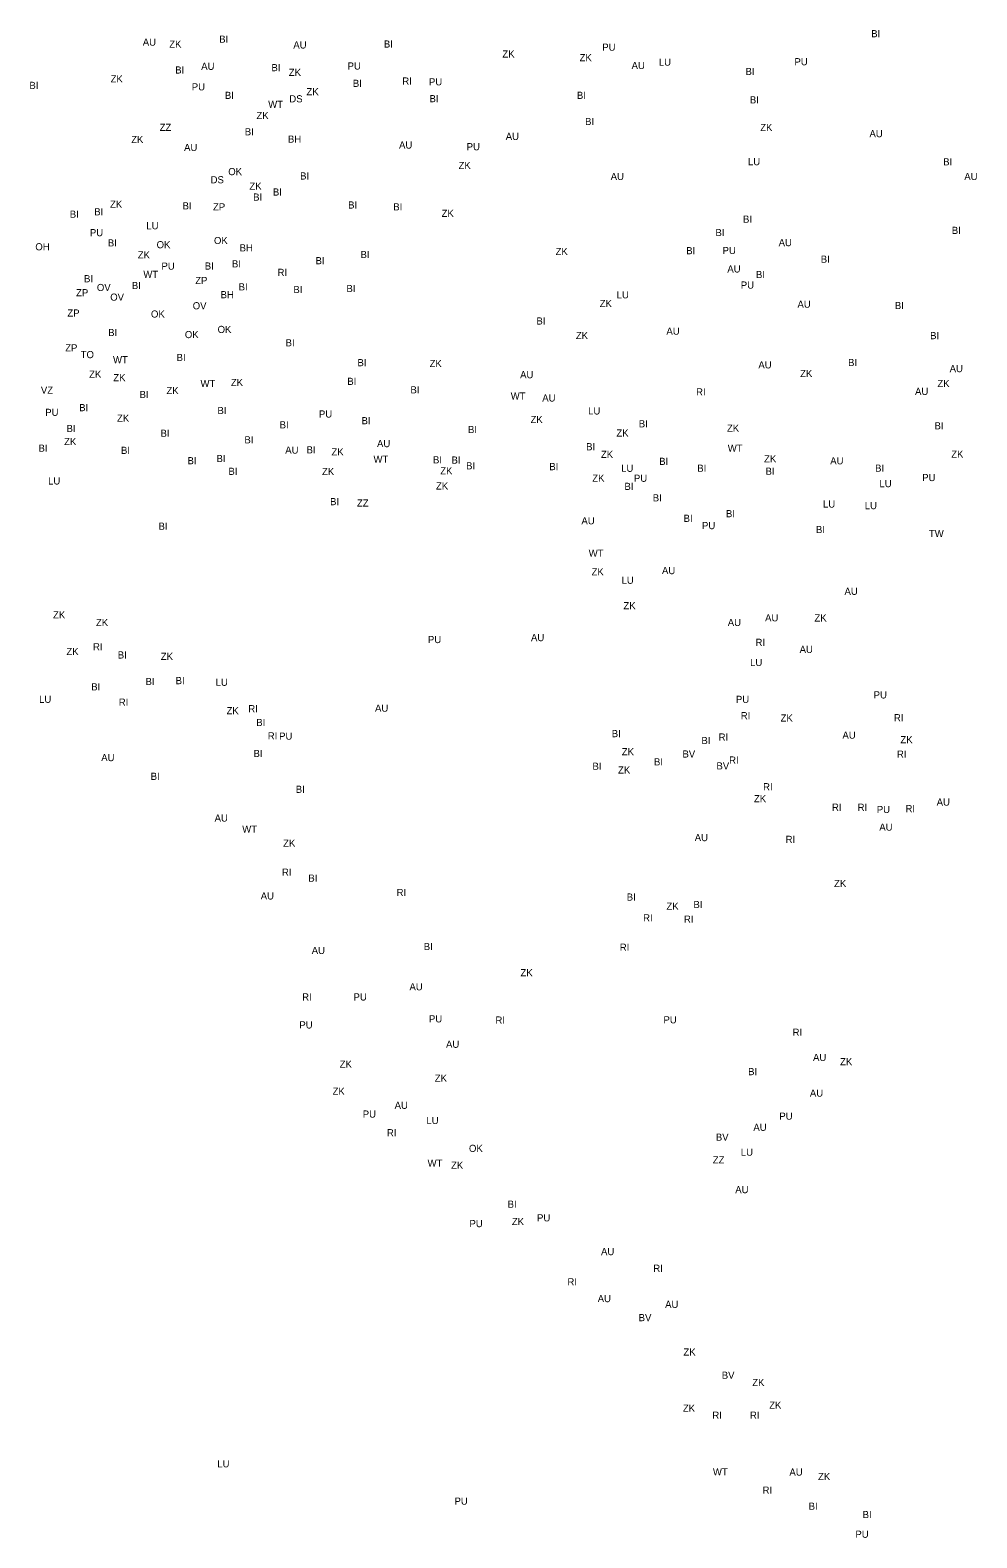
# Model space of a CAD drawing. Extents: x -439151 to -433911, y -1129946 to -1121460.
# Drawn here: x -437868 to -436541, y -1125705 to -1123591 of the extents above; entities that cross this region are included whole.
import ezdxf

# ---------------------------------------------------------------- set-up
doc = ezdxf.new("R2010")
doc.units = 0
doc.layers.add('POPIS PRESTAVBA', color=7, linetype='Continuous')
doc.layers.add('ZASTAVITELNA PLOCHA', color=7, linetype='Continuous')

msp = doc.modelspace()

# ---------------------------------------------------------------- texts
at = {"layer": 'POPIS PRESTAVBA'}
for s, p in [('AU', (-437709.7, -1123612.7)), ('BI', (-436688.8, -1123600.9)), ('ZK', (-437672.6, -1123615.5)), ('AU', (-437498.7, -1123616.7)), ('BI', (-437371.8, -1123615.4)), ('ZK', (-437205.7, -1123629.3)), ('PU', (-437065.7, -1123619.8)), ('AU', (-437627.8, -1123646.6)), ('BI', (-437529.4, -1123648.5)), ('ZK', (-437505, -1123655.1)), ('PU', (-437422.6, -1123646.2)), ('ZK', (-437097.5, -1123634.5)), ('AU', (-437024.6, -1123645.5)), ('LU', (-436986.4, -1123640.7)), ('BI', (-436864.9, -1123653.8)), ('PU', (-436796.3, -1123640.2)), ('BI', (-437868.6, -1123673.4)), ('ZK', (-437754.8, -1123664.3)), ('PU', (-437641, -1123675.4)), ('BI', (-437415.3, -1123670.5)), ('RI', (-437345.9, -1123667.3)), ('PU', (-437308.6, -1123668.4)), ('BI', (-437594.6, -1123687.4)), ('DS', (-437504.3, -1123692.2)), ('ZK', (-437480.2, -1123682.2)), ('BI', (-437307.8, -1123692)), ('BI', (-437101.2, -1123687.3)), ('BI', (-436858.8, -1123693.7)), ('ZK', (-437550.3, -1123715.6)), ('WT', (-437533.9, -1123699.9)), ('ZZ', (-437686, -1123732.2)), ('BI', (-437566.7, -1123738.4)), ('ZK', (-436844.3, -1123732.4)), ('ZK', (-437725.9, -1123749.2)), ('AU', (-437651.8, -1123760.4)), ('BH', (-437506.2, -1123748.7)), ('AU', (-437350.5, -1123757)), ('PU', (-437255.7, -1123759.4)), ('AU', (-437201, -1123744.9)), ('AU', (-436691.2, -1123741.1)), ('LU', (-436861.5, -1123780.4)), ('BI', (-436587.9, -1123780.6)), ('OK', (-437589.9, -1123794.3)), ('ZK', (-437267.1, -1123785.6)), ('AU', (-437053.9, -1123801.1)), ('AU', (-436558.3, -1123801.1)), ('DS', (-437614.6, -1123805.7)), ('ZK', (-437560.2, -1123814.6)), ('BI', (-437527.3, -1123822.9)), ('ZK', (-437755.6, -1123840)), ('BI', (-437653.9, -1123842.3)), ('ZP', (-437611.3, -1123843.7)), ('BI', (-437555, -1123830)), ('BI', (-437358.6, -1123843.7)), ('ZK', (-437290.9, -1123852.8)), ('BI', (-436868.4, -1123860.9)), ('PU', (-437783.8, -1123879.9)), ('LU', (-437704.7, -1123870.2)), ('BI', (-436575.8, -1123876.7)), ('OH', (-437860.3, -1123899.7)), ('BI', (-437758.6, -1123894.3)), ('OK', (-437690.3, -1123896.8)), ('OK', (-437609.9, -1123890.9)), ('BH', (-437573.9, -1123901.2)), ('ZK', (-437131.1, -1123906.3)), ('BI', (-436948, -1123905.2)), ('PU', (-436897.1, -1123904.9)), ('AU', (-436818.5, -1123893.9)), ('ZK', (-437716.7, -1123911.1)), ('PU', (-437683.5, -1123926.8)), ('BI', (-437622.8, -1123926.7)), ('BI', (-437584.7, -1123923.6)), ('BI', (-436759.5, -1123917.1)), ('BI', (-437792, -1123944.5)), ('WT', (-437708.9, -1123938.3)), ('ZP', (-437636.2, -1123947)), ('RI', (-437520.8, -1123935.6)), ('AU', (-436890.4, -1123930.8)), ('BI', (-436850.3, -1123938.7)), ('ZP', (-437803.2, -1123964.1)), ('OV', (-437755.3, -1123970.3)), ('BI', (-437725, -1123954)), ('BH', (-437600.6, -1123966.9)), ('BI', (-437575.3, -1123956)), ('BI', (-437424.2, -1123958.2)), ('LU', (-437045.5, -1123967)), ('PU', (-436871.5, -1123953.4)), ('ZP', (-437815.4, -1123992.6)), ('OK', (-437698.2, -1123994)), ('OV', (-437639.7, -1123982.4)), ('ZK', (-437069.3, -1123979.3)), ('AU', (-436792.1, -1123980.2)), ('BI', (-437158, -1124003.8)), ('BI', (-437758.2, -1124020)), ('OK', (-437650.7, -1124022.8)), ('OK', (-437604.8, -1124015.6)), ('BI', (-437509.5, -1124034.3)), ('ZK', (-437102.7, -1124024.2)), ('AU', (-436975.8, -1124018)), ('BI', (-436606.2, -1124024.3)), ('BI', (-437662.3, -1124054.9)), ('ZK', (-437784.8, -1124078.4)), ('WT', (-437751.4, -1124058.1)), ('BI', (-437408.8, -1124062.2)), ('ZK', (-437307.7, -1124063.5)), ('AU', (-436846.9, -1124065.3)), ('ZK', (-436788.3, -1124077.4)), ('BI', (-436721.2, -1124062)), ('AU', (-436578.8, -1124070.6)), ('ZK', (-437751, -1124083.2)), ('WT', (-437628.8, -1124091.5)), ('ZK', (-437586.2, -1124090)), ('AU', (-437180.8, -1124079.1)), ('ZK', (-436596, -1124091.5)), ('VZ', (-437852.5, -1124100.7)), ('BI', (-437714.2, -1124106.8)), ('ZK', (-437676.5, -1124101.4)), ('BI', (-437334.5, -1124100.3)), ('WT', (-437194, -1124108.9)), ('AU', (-437149.8, -1124111.8)), ('RI', (-436934.2, -1124103.2)), ('AU', (-436627.3, -1124102.5)), ('PU', (-437846.4, -1124131.9)), ('BI', (-437798.8, -1124125.3)), ('ZK', (-437745.8, -1124140)), ('BI', (-437605, -1124129.3)), ('PU', (-437462.8, -1124134.2)), ('ZK', (-437166.2, -1124141.9)), ('LU', (-437085.5, -1124129.9)), ('BI', (-437517.8, -1124149.3)), ('BI', (-437403.1, -1124143.6)), ('ZK', (-437045.9, -1124160.9)), ('BI', (-437014.5, -1124147.9)), ('ZK', (-436890.9, -1124154)), ('BI', (-436600, -1124150.7)), ('BI', (-437855.8, -1124182.1)), ('ZK', (-437819.9, -1124172.9)), ('BI', (-437567.2, -1124170.4)), ('AU', (-437381.4, -1124175.7)), ('WT', (-436889.8, -1124182.2)), ('BI', (-437740.2, -1124185.2)), ('BI', (-437647, -1124199.7)), ('BI', (-437606.3, -1124196.6)), ('AU', (-437510, -1124184.8)), ('ZK', (-437445.2, -1124187.3)), ('WT', (-437386.3, -1124197.6)), ('BI', (-437277, -1124198.8)), ('ZK', (-437067.6, -1124190.8)), ('ZK', (-436838.9, -1124197)), ('AU', (-436746.2, -1124199.8)), ('ZK', (-436576.6, -1124190.5)), ('ZK', (-437458.5, -1124214.8)), ('ZK', (-437292.8, -1124213.9)), ('BI', (-437139.9, -1124208)), ('ZK', (-437079.7, -1124224.1)), ('LU', (-437039.2, -1124210.3)), ('PU', (-437021.3, -1124224.3)), ('BI', (-436932.5, -1124210.3)), ('BI', (-436683.3, -1124210.1)), ('PU', (-436617.3, -1124223.3)), ('LU', (-437842.4, -1124228.1)), ('ZK', (-437298.8, -1124235.1)), ('LU', (-436677.2, -1124231.9)), ('BI', (-437447.2, -1124257.1)), ('ZZ', (-437409.5, -1124259)), ('BI', (-436994.9, -1124251.8)), ('LU', (-436756.3, -1124260.5)), ('LU', (-436697.8, -1124262.7)), ('AU', (-437094.9, -1124283.9)), ('BI', (-437687.6, -1124291.6)), ('PU', (-436925.9, -1124290.7)), ('TW', (-436607.9, -1124301.9)), ('WT', (-437084.7, -1124329.4)), ('ZK', (-437080.7, -1124355.5)), ('LU', (-437038.7, -1124367.3)), ('AU', (-436982, -1124353.8)), ('AU', (-436726.2, -1124382.8)), ('ZK', (-437835.5, -1124415.8)), ('ZK', (-437036, -1124403)), ('ZK', (-437775.3, -1124426.6)), ('AU', (-436889.8, -1124426.6)), ('AU', (-436837.5, -1124420)), ('ZK', (-436768.3, -1124420.2)), ('PU', (-437310, -1124450.5)), ('AU', (-437165.6, -1124447.8)), ('RI', (-436850.9, -1124454.4)), ('ZK', (-437816.7, -1124467.3)), ('RI', (-437779.4, -1124460.6)), ('BI', (-437744.7, -1124472.1)), ('ZK', (-437684.4, -1124474.1)), ('AU', (-436789.1, -1124464.3)), ('LU', (-436858.5, -1124482.6)), ('BI', (-437781.9, -1124516.8)), ('BI', (-437705.8, -1124509.3)), ('LU', (-437607.6, -1124510.4)), ('LU', (-437855, -1124534.3)), ('RI', (-437743.3, -1124538.3)), ('PU', (-436878.4, -1124534.4)), ('PU', (-436685.3, -1124528.1)), ('ZK', (-437592.3, -1124550.3)), ('RI', (-437561.8, -1124547.5)), ('AU', (-437384.2, -1124546.7)), ('RI', (-436871.6, -1124557.2)), ('ZK', (-436815.8, -1124560.5)), ('RI', (-436656.9, -1124560.1)), ('BI', (-437550.6, -1124566.7)), ('RI', (-437534.5, -1124585.6)), ('PU', (-437518.6, -1124585.9)), ('BI', (-437052.4, -1124582.4)), ('AU', (-436729.1, -1124584.5)), ('BI', (-436926.7, -1124592.1)), ('RI', (-436902.6, -1124587.2)), ('ZK', (-436647.8, -1124590.9)), ('AU', (-437767.9, -1124616)), ('BI', (-437079.4, -1124628.2)), ('ZK', (-437038.3, -1124607.8)), ('BI', (-436993.2, -1124622)), ('RI', (-436887.9, -1124619.5)), ('RI', (-436652.7, -1124611.1)), ('BI', (-437698.6, -1124642.3)), ('ZK', (-437043.6, -1124633.4)), ('BI', (-437495.3, -1124660.5)), ('RI', (-436840.3, -1124656.9)), ('ZK', (-436853.1, -1124673.6)), ('RI', (-436743.7, -1124685.7)), ('RI', (-436707.8, -1124685.7)), ('PU', (-436680.9, -1124688.8)), ('RI', (-436640.7, -1124687.6)), ('AU', (-436597, -1124678.4)), ('AU', (-437609, -1124700.8)), ('WT', (-437570.3, -1124716.3)), ('AU', (-436936.1, -1124728.2)), ('RI', (-436808.7, -1124730.7)), ('AU', (-436677.4, -1124713.5)), ('ZK', (-437512.9, -1124736)), ('RI', (-437514.6, -1124776.7)), ('BI', (-437477.6, -1124785)), ('ZK', (-436740.8, -1124792.5)), ('AU', (-437544.4, -1124810)), ('RI', (-437353.9, -1124805.2)), ('BI', (-437031.4, -1124811.6)), ('ZK', (-436975.7, -1124824.4)), ('BI', (-436937.9, -1124822)), ('RI', (-437008.4, -1124840.7)), ('RI', (-436951.2, -1124842.5)), ('BI', (-437315.9, -1124881)), ('AU', (-437472.9, -1124886.5)), ('RI', (-437041.1, -1124882)), ('ZK', (-437180.3, -1124917.7)), ('AU', (-437335.9, -1124937.4)), ('RI', (-437486.3, -1124951.7)), ('PU', (-437414.3, -1124951.7)), ('PU', (-437308.6, -1124982.4)), ('RI', (-437215.4, -1124984.1)), ('PU', (-436979.9, -1124983.7)), ('PU', (-437490.2, -1124990.9)), ('RI', (-436798.9, -1125001.2)), ('AU', (-437284.7, -1125018)), ('ZK', (-437433.7, -1125045.9)), ('AU', (-436770.3, -1125036.5)), ('ZK', (-436732.4, -1125042.5)), ('ZK', (-437300.4, -1125065.5)), ('BI', (-436861.3, -1125056.4)), ('ZK', (-437443.7, -1125083.9)), ('AU', (-436774.7, -1125086.5)), ('AU', (-437356.7, -1125103.6)), ('PU', (-437401.4, -1125115.9)), ('LU', (-437312.2, -1125124.9)), ('AU', (-436853.9, -1125134.5)), ('PU', (-436817.5, -1125118.8)), ('RI', (-437367.5, -1125142.1)), ('BV', (-436906.5, -1125148.3)), ('OK', (-437252.5, -1125164)), ('LU', (-436871.5, -1125169.3)), ('WT', (-437310.5, -1125184.8)), ('ZK', (-437277.6, -1125187.7)), ('ZZ', (-436910.8, -1125180.2)), ('AU', (-436879.3, -1125221.9)), ('BI', (-437198.3, -1125242.3)), ('PU', (-437157.1, -1125261.4)), ('PU', (-437251.8, -1125269.5)), ('ZK', (-437192.4, -1125266.7)), ('AU', (-437067.4, -1125308.8)), ('RI', (-436994.1, -1125332.2)), ('RI', (-437114.5, -1125351.1)), ('AU', (-437072.1, -1125374.7)), ('AU', (-436977.6, -1125382.8)), ('ZK', (-436951.9, -1125449.6)), ('BV', (-436898.2, -1125482.2)), ('ZK', (-436855.5, -1125492.3)), ('ZK', (-436952.7, -1125528.4)), ('ZK', (-436831.7, -1125524.1)), ('RI', (-436911.4, -1125538.2)), ('RI', (-436858.7, -1125538.2)), ('LU', (-437605.3, -1125606.3)), ('WT', (-436910.6, -1125617.6)), ('AU', (-436803.4, -1125617.9)), ('ZK', (-436763.3, -1125624.2)), ('PU', (-437272.8, -1125658.7)), ('RI', (-436841, -1125643.2)), ('BI', (-436776.4, -1125665.9)), ('BI', (-436700.8, -1125677.6)), ('PU', (-436710.9, -1125705.1))]:
    msp.add_text(s, height=10, dxfattribs=at).set_placement(p)
at = {"layer": 'ZASTAVITELNA PLOCHA'}
for s, p in [('BI', (-437602.6, -1123608.5)), ('BI', (-437664.2, -1123651.8)), ('BI', (-437089.8, -1123723.9)), ('BI', (-437489.2, -1123800.4)), ('BI', (-437421.9, -1123841.1)), ('BI', (-437812, -1123854)), ('BI', (-437777.7, -1123850.6)), ('BI', (-436907, -1123879.8)), ('BI', (-437467.5, -1123919.2)), ('BI', (-437404.5, -1123910.5)), ('OV', (-437774, -1123956.8)), ('BI', (-437498.6, -1123959.7)), ('BI', (-436655.6, -1123982.1)), ('ZP', (-437818.4, -1124041.4)), ('TO', (-437796.7, -1124050.9)), ('BI', (-437423, -1124088.4)), ('BI', (-437816.5, -1124154.5)), ('BI', (-437684.8, -1124161.2)), ('BI', (-437253.9, -1124156)), ('BI', (-437088.3, -1124180.1)), ('BI', (-437480.1, -1124184.5)), ('BI', (-437302.9, -1124198.4)), ('BI', (-436985.9, -1124200.6)), ('BI', (-437589.7, -1124214.6)), ('BI', (-437256.6, -1124206.8)), ('BI', (-436836.8, -1124214.5)), ('BI', (-437034.6, -1124235.7)), ('BI', (-436951.7, -1124280.5)), ('BI', (-436892.3, -1124274)), ('BI', (-436766.2, -1124296.3)), ('BI', (-437663.6, -1124508.1)), ('BI', (-437554.5, -1124610.2)), ('BV', (-436953.3, -1124611)), ('BV', (-436905.6, -1124627.7)), ('BV', (-437014.7, -1125401.4))]:
    msp.add_text(s, height=10, dxfattribs=at).set_placement(p)

doc.saveas('drawing.dxf')
